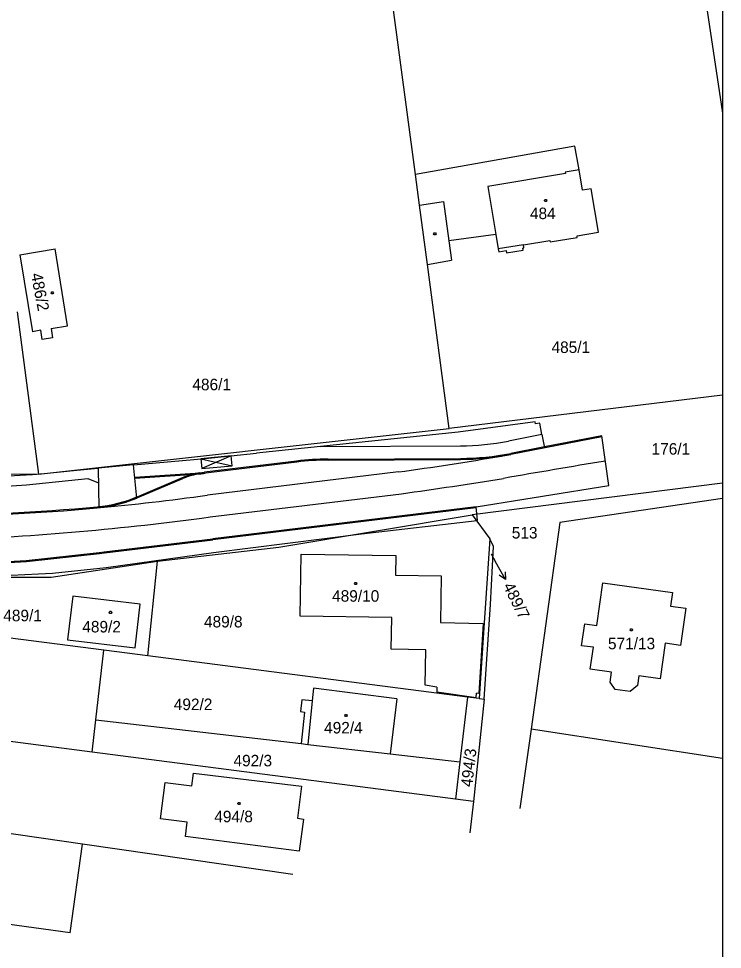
# Model space of a CAD drawing. Extents: x -639621 to -639329, y -1192893 to -1192488.
# Drawn here: x -639433 to -639329.3, y -1192784.9 to -1192647.6 of the extents above; entities that cross this region are included whole.
import ezdxf

# ---------------------------------------------------------------- set-up
doc = ezdxf.new("R2010")
doc.units = 0
for name, color, linetype in [('Vrstva 1', 7, 'Continuous'), ('Vrstva 19', 7, 'Continuous'), ('Vrstva 2', 7, 'Continuous'), ('Vrstva 20', 7, 'Continuous'), ('Vrstva 22', 7, 'Continuous'), ('Vrstva 4', 7, 'Continuous'), ('Vrstva 5', 7, 'Continuous'), ('Vrstva 61', 7, 'Continuous'), ('Vrstva 7', 7, 'Continuous')]:
    doc.layers.add(name, color=color, linetype=linetype)

msp = doc.modelspace()

# ---------------------------------------------------------------- linework, layer by layer
at = {"layer": 'Vrstva 1'}
for p, q in [((-639334.13, -1192628.53), (-639329.26, -1192661.57)), ((-639374.53, -1192670.58), (-639379.36, -1192634.4)), ((-639351.01, -1192666.42), (-639374.53, -1192670.58)), ((-639350.4, -1192669.9), (-639351.01, -1192666.42)), ((-639349.87, -1192672.92), (-639350.4, -1192669.9)), ((-639373.92, -1192675.15), (-639374.53, -1192670.58)), ((-639348.62, -1192672.7), (-639349.87, -1192672.92)), ((-639347.51, -1192679.11), (-639348.62, -1192672.7)), ((-639372.76, -1192683.86), (-639373.92, -1192675.15)), ((-639362.66, -1192679.45), (-639369.6, -1192680.38)), ((-639362.66, -1192679.45), (-639362.3, -1192681.59)), ((-639350.69, -1192679.66), (-639347.51, -1192679.11)), ((-639350.65, -1192679.89), (-639350.69, -1192679.66)), ((-639369.6, -1192680.38), (-639369.22, -1192683.23)), ((-639358.58, -1192680.97), (-639354.68, -1192680.32)), ((-639358.51, -1192681.43), (-639358.58, -1192680.97)), ((-639354.68, -1192680.32), (-639354.64, -1192680.55)), ((-639354.64, -1192680.55), (-639350.65, -1192679.89)), ((-639432.82, -1192682.46), (-639427.64, -1192681.59)), ((-639432.82, -1192682.46), (-639430.98, -1192693.81)), ((-639425.81, -1192692.93), (-639427.64, -1192681.59)), ((-639362.3, -1192681.59), (-639362.23, -1192681.99)), ((-639362.23, -1192681.99), (-639361.16, -1192681.81)), ((-639361.16, -1192681.81), (-639361.1, -1192682.17)), ((-639361.1, -1192682.17), (-639358.61, -1192681.76)), ((-639358.66, -1192681.45), (-639358.51, -1192681.43)), ((-639358.61, -1192681.76), (-639358.66, -1192681.45)), ((-639372.76, -1192683.86), (-639369.22, -1192683.23)), ((-639369.53, -1192708.06), (-639372.76, -1192683.86)), ((-639433.22, -1192690.86), (-639430.11, -1192714.81)), ((-639429.75, -1192693.59), (-639430.98, -1192693.81)), ((-639429.53, -1192694.94), (-639429.75, -1192693.59)), ((-639428.23, -1192693.34), (-639425.81, -1192692.93)), ((-639428.23, -1192693.34), (-639428.01, -1192694.7)), ((-639428.01, -1192694.7), (-639429.53, -1192694.94)), ((-639329.26, -1192703.15), (-639369.53, -1192708.06)), ((-639430.11, -1192714.81), (-639369.53, -1192708.06)), ((-639430.11, -1192714.81), (-639485.5, -1192715.26)), ((-639329.26, -1192716.12), (-639366.16, -1192720.83)), ((-639329.26, -1192718.4), (-639353.22, -1192721.94)), ((-639394.64, -1192725.58), (-639366.16, -1192720.83)), ((-639366.16, -1192720.83), (-639363.55, -1192724.33)), ((-639353.22, -1192721.94), (-639357.47, -1192752.43)), ((-639363.55, -1192724.33), (-639364.42, -1192737.47)), ((-639363.02, -1192725.47), (-639363.55, -1192724.33)), ((-639412.53, -1192727.63), (-639394.64, -1192725.58)), ((-639363.45, -1192734.05), (-639363.02, -1192725.47)), ((-639428.21, -1192730.01), (-639412.53, -1192727.63)), ((-639413.99, -1192741.6), (-639412.53, -1192727.63)), ((-639391.52, -1192735.73), (-639391.38, -1192726.63)), ((-639391.38, -1192726.63), (-639377.39, -1192726.82)), ((-639377.39, -1192726.82), (-639377.44, -1192729.71)), ((-639449.52, -1192729.95), (-639428.21, -1192730.01)), ((-639377.44, -1192729.71), (-639370.74, -1192729.81)), ((-639370.74, -1192729.81), (-639370.8, -1192736.7)), ((-639347.79, -1192737.11), (-639346.87, -1192730.83)), ((-639346.87, -1192730.83), (-639336.62, -1192732.28)), ((-639425.02, -1192732.78), (-639425.8, -1192739.27)), ((-639415.08, -1192733.98), (-639425.02, -1192732.78)), ((-639336.62, -1192732.28), (-639336.9, -1192734.26)), ((-639415.86, -1192740.42), (-639415.08, -1192733.98)), ((-639364.37, -1192748.01), (-639363.45, -1192734.05)), ((-639336.9, -1192734.26), (-639334.64, -1192734.59)), ((-639334.64, -1192734.59), (-639335.46, -1192740.09)), ((-639378.02, -1192735.94), (-639391.52, -1192735.73)), ((-639378.09, -1192740.64), (-639378.02, -1192735.94)), ((-639420.45, -1192740.76), (-639446.92, -1192737.34)), ((-639370.8, -1192736.7), (-639364.51, -1192736.84)), ((-639364.51, -1192736.84), (-639365.17, -1192747.18)), ((-639364.42, -1192737.47), (-639365.12, -1192747.91)), ((-639350.02, -1192740.11), (-639349.53, -1192736.9)), ((-639349.53, -1192736.9), (-639347.79, -1192737.11)), ((-639425.8, -1192739.27), (-639415.86, -1192740.42)), ((-639348.27, -1192740.32), (-639350.02, -1192740.11)), ((-639337.69, -1192739.76), (-639338.44, -1192745.02)), ((-639335.46, -1192740.09), (-639337.69, -1192739.76)), ((-639421.62, -1192751.04), (-639420.45, -1192740.76)), ((-639413.99, -1192741.6), (-639420.45, -1192740.76)), ((-639366.85, -1192747.69), (-639413.99, -1192741.6)), ((-639372.99, -1192740.72), (-639378.09, -1192740.64)), ((-639373.07, -1192745.94), (-639372.99, -1192740.72)), ((-639348.74, -1192743.57), (-639348.27, -1192740.32)), ((-639345.62, -1192744.01), (-639348.74, -1192743.57)), ((-639345.79, -1192745.47), (-639345.62, -1192744.01)), ((-639345.05, -1192746.57), (-639345.79, -1192745.47)), ((-639341.56, -1192744.58), (-639341.79, -1192745.98)), ((-639338.44, -1192745.02), (-639341.56, -1192744.58)), ((-639389.56, -1192746.39), (-639389.75, -1192748.26)), ((-639377.26, -1192747.97), (-639389.56, -1192746.39)), ((-639371.35, -1192746.21), (-639373.07, -1192745.94)), ((-639371.35, -1192746.21), (-639371.36, -1192746.91)), ((-639371.36, -1192746.91), (-639365.54, -1192747.74)), ((-639365.54, -1192747.74), (-639365.5, -1192747.13)), ((-639365.17, -1192747.18), (-639365.5, -1192747.13)), ((-639342.85, -1192746.88), (-639345.05, -1192746.57)), ((-639341.79, -1192745.98), (-639342.85, -1192746.88)), ((-639391.25, -1192748.09), (-639391.45, -1192749.83)), ((-639389.75, -1192748.26), (-639391.25, -1192748.09)), ((-639377.26, -1192747.97), (-639378.25, -1192756.07)), ((-639366.85, -1192747.69), (-639367.98, -1192757.26)), ((-639365.12, -1192747.91), (-639366.85, -1192747.69)), ((-639364.37, -1192748.01), (-639365.94, -1192763.11)), ((-639365.12, -1192747.91), (-639364.37, -1192748.01)), ((-639391.45, -1192749.83), (-639390.85, -1192749.9)), ((-639422.16, -1192755.8), (-639457.18, -1192751.25)), ((-639422.16, -1192755.8), (-639421.62, -1192751.04)), ((-639421.62, -1192751.04), (-639391.38, -1192754.55)), ((-639390.85, -1192749.9), (-639391.38, -1192754.55)), ((-639357.47, -1192752.43), (-639359.1, -1192764.13)), ((-639329.26, -1192756.74), (-639357.47, -1192752.43)), ((-639391.38, -1192754.55), (-639390.38, -1192754.67)), ((-639390.38, -1192754.67), (-639378.25, -1192756.07)), ((-639368.63, -1192762.76), (-639422.16, -1192755.8)), ((-639378.25, -1192756.07), (-639367.98, -1192757.26)), ((-639367.98, -1192757.26), (-639368.63, -1192762.76)), ((-639407.49, -1192760.78), (-639407.26, -1192758.89)), ((-639407.26, -1192758.89), (-639391.33, -1192760.84)), ((-639412.08, -1192765.64), (-639411.41, -1192760.27)), ((-639411.41, -1192760.27), (-639407.49, -1192760.78)), ((-639391.33, -1192760.84), (-639391.92, -1192765.56)), ((-639423.61, -1192769.39), (-639465.28, -1192763.39)), ((-639365.94, -1192763.11), (-639368.63, -1192762.76)), ((-639365.94, -1192763.11), (-639366.5, -1192767.72)), ((-639408.16, -1192766.14), (-639412.08, -1192765.64)), ((-639408.42, -1192768.25), (-639408.16, -1192766.14)), ((-639391.92, -1192765.56), (-639391.03, -1192765.68)), ((-639391.03, -1192765.68), (-639391.65, -1192770.4)), ((-639391.65, -1192770.4), (-639408.42, -1192768.25)), ((-639425.4, -1192782.45), (-639423.61, -1192769.39)), ((-639392.61, -1192773.86), (-639423.61, -1192769.39)), ((-639425.4, -1192782.45), (-639473.03, -1192775.94))]:
    msp.add_line(p, q, dxfattribs=at)
at = {"layer": 'Vrstva 19'}
for p, q in [((-639347.02, -1192709.29), (-639360.43, -1192711.9)), ((-639347.04, -1192709.14), (-639355.5, -1192710.79)), ((-639346.01, -1192716.46), (-639347.04, -1192709.14)), ((-639352.74, -1192710.25), (-639352.71, -1192710.4)), ((-639387.39, -1192712.73), (-639367.86, -1192712.63)), ((-639392.01, -1192713.02), (-639406.26, -1192714.76)), ((-639415.42, -1192718.27), (-639408.8, -1192715.46)), ((-639377.01, -1192714.47), (-639405.19, -1192717.89)), ((-639365.58, -1192719.63), (-639346.01, -1192716.46)), ((-639365.58, -1192719.63), (-639404.4, -1192724.35)), ((-639420.39, -1192726.28), (-639404.4, -1192724.35))]:
    msp.add_line(p, q, dxfattribs=at)
for points in [[(-639404.8, -1192721.12), (-639376.59, -1192717.7)], [(-639449.51, -1192728.26), (-639445.16, -1192728.22), (-639436.4, -1192727.78), (-639431.89, -1192727.55), (-639421.13, -1192726.37), (-639420.39, -1192726.28)]]:
    msp.add_lwpolyline(points, dxfattribs=at)
for centre, radius, start, end in [((-639387.19, -1192752.73), 40, 90.2886, 96.9216), ((-639438.41, -1192265), 453.65, 277.7754, 279.7171), ((-639368.06, -1192672.63), 40, 270.2886, 280.9952), ((-639042.3, -1194545.41), 1857.62, 99.4256, 99.89543), ((-639404.9, -1192724.67), 10, 97.8346, 112.9652), ((-639474.85, -1192216.31), 503.15, 277.8346, 277.9132), ((-639467.42, -1192063.15), 660.82, 277.90065, 279.22092), ((-639451.84, -1192385.67), 335.49, 275.2029, 277.9853), ((-639423.23, -1192699.85), 20, 275.2029, 292.9652), ((-639423.33, -1192699.36), 20.51, 279.3256, 292.1416), ((-639451.84, -1192385.67), 335.49, 270.6612, 275.2029), ((-639460.64, -1192306.47), 418.4, 272.3713, 277.6707)]:
    msp.add_arc(centre, radius, start, end, dxfattribs=at)
at = {"layer": 'Vrstva 20'}
for p, q in [((-639355.86, -1192708.97), (-639360.81, -1192709.93)), ((-639355.86, -1192708.97), (-639355.48, -1192710.93)), ((-639388.51, -1192710.73), (-639397.97, -1192711.73)), ((-639388.54, -1192710.73), (-639367.87, -1192710.63)), ((-639355.5, -1192710.79), (-639360.46, -1192711.75)), ((-639416.08, -1192713.41), (-639405.52, -1192712.49)), ((-639406.16, -1192712.55), (-639401.54, -1192713.56)), ((-639401.68, -1192712.12), (-639406.02, -1192713.99)), ((-639405.52, -1192712.49), (-639397.97, -1192711.73)), ((-639387.39, -1192712.58), (-639367.86, -1192712.48)), ((-639392.03, -1192712.87), (-639405.6, -1192714.52)), ((-639415.9, -1192715.25), (-639406.27, -1192714.61)), ((-639415.89, -1192715.4), (-639406.26, -1192714.76)), ((-639415.62, -1192718.19), (-639408.86, -1192715.32)), ((-639365.63, -1192719.64), (-639365.4, -1192721.63)), ((-639365.62, -1192719.79), (-639404.39, -1192724.5)), ((-639382.48, -1192723.63), (-639365.4, -1192721.63)), ((-639404.29, -1192726.34), (-639382.48, -1192723.63)), ((-639420.37, -1192726.43), (-639404.39, -1192724.5)), ((-639420.11, -1192728.56), (-639404.29, -1192726.34)), ((-639428.05, -1192729.42), (-639420.11, -1192728.56)), ((-639444.59, -1192730.2), (-639430.08, -1192729.53)), ((-639430.08, -1192729.53), (-639428.05, -1192729.42))]:
    msp.add_line(p, q, dxfattribs=at)
msp.add_lwpolyline([(-639406.02, -1192713.99), (-639401.54, -1192713.56), (-639401.68, -1192712.12), (-639406.16, -1192712.55)], close=True, dxfattribs=at)
for points in [[(-639450.17, -1192715.78), (-639446.25, -1192715.6), (-639442.69, -1192715.44), (-639438.85, -1192715.26), (-639435.33, -1192715.1), (-639432.77, -1192714.98), (-639430.98, -1192714.85), (-639429.27, -1192714.69), (-639424.43, -1192714.23), (-639421.28, -1192713.93)], [(-639416.08, -1192713.41), (-639421.28, -1192713.93), (-639421.19, -1192719.75)], [(-639415.6, -1192718.35), (-639416.08, -1192713.41)], [(-639449.56, -1192717.46), (-639446.75, -1192717.35), (-639431.85, -1192716.39), (-639422.84, -1192715.45), (-639421.25, -1192716.08)], [(-639449.5, -1192728.41), (-639445.15, -1192728.37), (-639436.39, -1192727.92), (-639431.88, -1192727.7), (-639421.11, -1192726.52), (-639420.37, -1192726.43)]]:
    msp.add_lwpolyline(points, dxfattribs=at)
for centre, radius, start, end in [((-639368.06, -1192672.63), 38, 270.2886, 280.9952), ((-639387.19, -1192752.73), 40.15, 90.2886, 96.9216), ((-639368.06, -1192672.63), 39.85, 270.2886, 280.9952), ((-639404.9, -1192724.67), 10.15, 97.8346, 112.9652), ((-639474.85, -1192216.31), 503, 277.8346, 277.9132), ((-639423.23, -1192699.85), 19.85, 275.2029, 292.9652), ((-639451.84, -1192385.67), 335.34, 270.6612, 275.2029)]:
    msp.add_arc(centre, radius, start, end, dxfattribs=at)
at = {"layer": 'Vrstva 22'}
msp.add_lwpolyline([(-639355.86, -1192708.97), (-639356.19, -1192707.28), (-639356.79, -1192707.4), (-639356.85, -1192707.1), (-639368.22, -1192708.61), (-639388.51, -1192710.73)], dxfattribs=at)
at = {"layer": 'Vrstva 4'}
for p, q in [((-639350.4, -1192669.9), (-639352.43, -1192670.24)), ((-639352.43, -1192670.24), (-639352.4, -1192670.45)), ((-639352.4, -1192670.45), (-639363.85, -1192672.38)), ((-639363.85, -1192672.38), (-639362.66, -1192679.45)), ((-639373.92, -1192675.15), (-639370.36, -1192674.6)), ((-639370.36, -1192674.6), (-639369.6, -1192680.38)), ((-639358.58, -1192680.97), (-639362.3, -1192681.59)), ((-639389.75, -1192748.26), (-639390.38, -1192754.67))]:
    msp.add_line(p, q, dxfattribs=at)
at = {"layer": 'Vrstva 5'}
for points in [[(-639355.24, -1192674.3), (-639355.15, -1192674.45), (-639355.24, -1192674.6), (-639355.42, -1192674.6), (-639355.51, -1192674.45), (-639355.42, -1192674.3)], [(-639371.57, -1192679.2), (-639371.48, -1192679.35), (-639371.57, -1192679.5), (-639371.75, -1192679.5), (-639371.84, -1192679.35), (-639371.75, -1192679.2)], [(-639427.96, -1192687.93), (-639427.87, -1192688.08), (-639427.96, -1192688.23), (-639428.14, -1192688.23), (-639428.23, -1192688.08), (-639428.14, -1192687.93)], [(-639383.23, -1192730.77), (-639383.14, -1192730.92), (-639383.23, -1192731.07), (-639383.41, -1192731.07), (-639383.5, -1192730.92), (-639383.41, -1192730.77)], [(-639419.38, -1192735.04), (-639419.29, -1192735.19), (-639419.38, -1192735.34), (-639419.56, -1192735.34), (-639419.65, -1192735.19), (-639419.56, -1192735.04)], [(-639342.58, -1192737.6), (-639342.49, -1192737.75), (-639342.58, -1192737.9), (-639342.76, -1192737.9), (-639342.85, -1192737.75), (-639342.76, -1192737.6)], [(-639384.67, -1192750.25), (-639384.58, -1192750.4), (-639384.67, -1192750.55), (-639384.85, -1192750.55), (-639384.94, -1192750.4), (-639384.85, -1192750.25)], [(-639400.45, -1192763.25), (-639400.36, -1192763.4), (-639400.45, -1192763.55), (-639400.63, -1192763.55), (-639400.72, -1192763.4), (-639400.63, -1192763.25)]]:
    msp.add_lwpolyline(points, close=True, dxfattribs=at)
at = {"layer": 'Vrstva 61'}
msp.add_lwpolyline([(-639329.26, -1192487.83), (-639329.26, -1192893.33)], dxfattribs=at)
at = {"layer": 'Vrstva 7'}
for p in [(-639363.36, -1192726.57), (-639361.22, -1192730.33)]:
    msp.add_line(p, (-639362.7, -1192727.72), dxfattribs=at)
msp.add_lwpolyline([(-639361.28, -1192729.21), (-639361.22, -1192730.33), (-639362.15, -1192729.71)], dxfattribs=at)

# ---------------------------------------------------------------- texts
at = {"layer": 'Vrstva 2'}
for s, height, p in [('484', 1.7, (-639357.63, -1192677.19)), ('485/1', 1.7, (-639354.45, -1192696.93)), ('486/1', 1.7, (-639407.4, -1192702.43)), ('176/1', 1.7, (-639339.7, -1192711.93)), ('513', 1.7, (-639360.31, -1192724.3)), ('489/7', 0.1, (-639363.56, -1192726.57)), ('489/10', 1.7, (-639386.8, -1192733.62)), ('489/1', 1.7, (-639435.28, -1192736.51)), ('489/8', 1.7, (-639405.69, -1192737.42)), ('489/2', 1.7, (-639423.63, -1192738.16)), ('571/13', 1.7, (-639346.13, -1192740.64)), ('492/2', 1.7, (-639410.14, -1192749.61)), ('492/4', 1.7, (-639387.98, -1192753.06)), ('492/3', 1.7, (-639401.34, -1192757.91)), ('494/8', 1.7, (-639404.17, -1192766.16))]:
    msp.add_text(s, height=height, dxfattribs=at).set_placement(p)
for s, rotation, p in [('486/2', 280.8639, (-639431.22, -1192685.29)), ('494/3', 83.5945, (-639366.14, -1192761.02))]:
    msp.add_text(s, height=1.7, rotation=rotation, dxfattribs=at).set_placement(p)
at = {"layer": 'Vrstva 7'}
msp.add_text('489/7', height=1.7, rotation=296.3338, dxfattribs=at).set_placement((-639361.64, -1192731.3))

doc.saveas('drawing.dxf')
